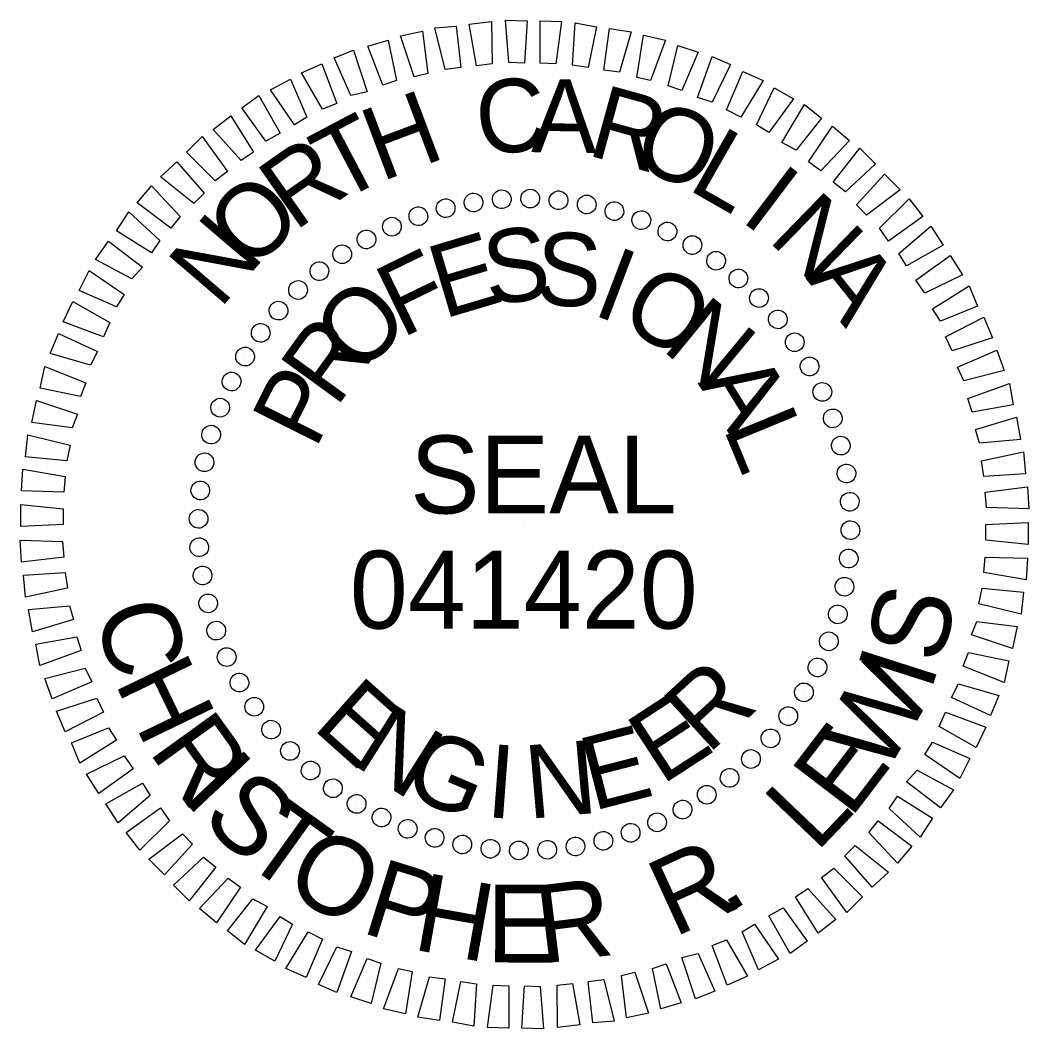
# Model space of a CAD drawing. Extents: x 573468 to 580768, y -57414 to -51768.
# Drawn here: x 580690.5 to 580768.1, y -56457.1 to -56379.5 of the extents above; entities that cross this region are included whole.
import ezdxf

# ---------------------------------------------------------------- set-up
doc = ezdxf.new("R2010")
doc.units = 0
doc.layers.add('Sheet PE Seal Cell', color=7, linetype='Continuous')

msp = doc.modelspace()

# ---------------------------------------------------------------- linework, layer by layer
at = {"layer": 'Sheet PE Seal Cell'}
for p, q in [((580727.529, -56393.239), (580727.529, -56393.239)), ((580729.729, -56393.189), (580729.729, -56393.189)), ((580731.929, -56393.339), (580731.929, -56393.339)), ((580723.179, -56393.939), (580723.179, -56393.939)), ((580725.379, -56393.539), (580725.379, -56393.539)), ((580734.079, -56393.689), (580734.079, -56393.689)), ((580736.179, -56394.139), (580736.179, -56394.139)), ((580721.079, -56394.539), (580721.079, -56394.539)), ((580738.279, -56394.839), (580738.279, -56394.839)), ((580719.079, -56395.339), (580719.079, -56395.339)), ((580740.279, -56395.739), (580740.279, -56395.739)), ((580717.129, -56396.339), (580717.129, -56396.339)), ((580742.229, -56396.739), (580742.229, -56396.739)), ((580715.229, -56397.489), (580715.229, -56397.489)), ((580744.029, -56397.989), (580744.029, -56397.989)), ((580713.479, -56398.739), (580713.479, -56398.739)), ((580745.779, -56399.339), (580745.779, -56399.339)), ((580711.829, -56400.239), (580711.829, -56400.239)), ((580747.329, -56400.839), (580747.329, -56400.839)), ((580710.329, -56401.789), (580710.329, -56401.789)), ((580748.829, -56402.489), (580748.829, -56402.489)), ((580708.979, -56403.539), (580708.979, -56403.539)), ((580750.079, -56404.239), (580750.079, -56404.239)), ((580707.729, -56405.339), (580707.729, -56405.339)), ((580751.229, -56406.139), (580751.229, -56406.139)), ((580706.729, -56407.289), (580706.729, -56407.289)), ((580752.229, -56408.089), (580752.229, -56408.089)), ((580705.829, -56409.289), (580705.829, -56409.289)), ((580753.029, -56410.089), (580753.029, -56410.089)), ((580705.129, -56411.389), (580705.129, -56411.389)), ((580753.629, -56412.189), (580753.629, -56412.189)), ((580704.679, -56413.489), (580704.679, -56413.489)), ((580754.029, -56414.389), (580754.029, -56414.389)), ((580704.329, -56415.639), (580704.329, -56415.639)), ((580754.329, -56416.539), (580754.329, -56416.539)), ((580704.179, -56417.839), (580704.179, -56417.839)), ((580729.279, -56418.289), (580729.279, -56418.289)), ((580754.379, -56418.739), (580754.379, -56418.739)), ((580704.229, -56420.039), (580704.229, -56420.039)), ((580754.229, -56420.939), (580754.229, -56420.939)), ((580704.529, -56422.189), (580704.529, -56422.189)), ((580753.879, -56423.089), (580753.879, -56423.089)), ((580704.929, -56424.389), (580704.929, -56424.389)), ((580753.429, -56425.189), (580753.429, -56425.189)), ((580705.529, -56426.489), (580705.529, -56426.489)), ((580752.729, -56427.289), (580752.729, -56427.289)), ((580706.329, -56428.489), (580706.329, -56428.489)), ((580751.829, -56429.289), (580751.829, -56429.289)), ((580707.329, -56430.439), (580707.329, -56430.439)), ((580750.829, -56431.239), (580750.829, -56431.239)), ((580708.479, -56432.339), (580708.479, -56432.339)), ((580749.579, -56433.039), (580749.579, -56433.039)), ((580709.729, -56434.089), (580709.729, -56434.089)), ((580748.229, -56434.789), (580748.229, -56434.789)), ((580711.229, -56435.739), (580711.229, -56435.739)), ((580746.729, -56436.339), (580746.729, -56436.339)), ((580712.779, -56437.239), (580712.779, -56437.239)), ((580745.079, -56437.839), (580745.079, -56437.839)), ((580714.529, -56438.589), (580714.529, -56438.589)), ((580743.329, -56439.089), (580743.329, -56439.089)), ((580716.329, -56439.839), (580716.329, -56439.839)), ((580741.429, -56440.239), (580741.429, -56440.239)), ((580718.279, -56440.839), (580718.279, -56440.839)), ((580739.479, -56441.239), (580739.479, -56441.239)), ((580720.279, -56441.739), (580720.279, -56441.739)), ((580737.479, -56442.039), (580737.479, -56442.039)), ((580722.379, -56442.439), (580722.379, -56442.439)), ((580724.479, -56442.889), (580724.479, -56442.889)), ((580733.179, -56443.039), (580733.179, -56443.039)), ((580735.379, -56442.639), (580735.379, -56442.639)), ((580726.629, -56443.239), (580726.629, -56443.239)), ((580728.829, -56443.389), (580728.829, -56443.389)), ((580731.029, -56443.339), (580731.029, -56443.339))]:
    msp.add_line(p, q, dxfattribs=at)
for points in [[(580728.079, -56382.739), (580727.829, -56379.489), (580729.479, -56379.539), (580729.279, -56382.789)], [(580723.179, -56383.289), (580722.379, -56380.089), (580724.029, -56379.939), (580724.379, -56383.139)], [(580725.579, -56382.989), (580725.029, -56379.789), (580726.729, -56379.589), (580726.779, -56382.839)], [(580730.479, -56382.789), (580730.479, -56379.539), (580732.129, -56379.589), (580731.679, -56382.839)], [(580732.979, -56382.939), (580733.179, -56379.689), (580734.829, -56379.989), (580734.179, -56383.139)], [(580735.379, -56383.339), (580735.829, -56380.139), (580737.479, -56380.389), (580736.579, -56383.489)], [(580718.379, -56384.489), (580717.229, -56381.489), (580718.779, -56381.039), (580719.429, -56384.139)], [(580720.779, -56383.839), (580719.729, -56380.689), (580721.429, -56380.339), (580721.829, -56383.589)], [(580737.929, -56383.889), (580738.429, -56380.639), (580740.129, -56381.039), (580738.979, -56384.139)], [(580715.929, -56385.289), (580714.629, -56382.389), (580716.129, -56381.789), (580717.179, -56384.989)], [(580740.329, -56384.539), (580741.079, -56381.439), (580742.629, -56381.939), (580741.379, -56384.889)], [(580742.579, -56385.439), (580743.729, -56382.289), (580745.129, -56382.889), (580743.729, -56385.789)], [(580713.729, -56386.339), (580712.129, -56383.539), (580713.679, -56382.839), (580714.829, -56385.889)], [(580711.579, -56387.539), (580709.729, -56384.839), (580711.279, -56384.039), (580712.529, -56386.939)], [(580744.829, -56386.389), (580746.079, -56383.439), (580747.629, -56384.139), (580745.929, -56386.939)], [(580747.129, -56387.539), (580748.479, -56384.689), (580749.979, -56385.539), (580748.079, -56388.139)], [(580709.379, -56388.789), (580707.529, -56386.239), (580708.829, -56385.289), (580710.479, -56388.189)], [(580749.079, -56388.889), (580750.829, -56385.989), (580752.129, -56387.039), (580750.179, -56389.489)], [(580707.479, -56390.289), (580705.329, -56387.889), (580706.679, -56386.839), (580708.429, -56389.639)], [(580751.129, -56390.389), (580752.979, -56387.639), (580754.279, -56388.739), (580752.079, -56391.089)], [(580705.479, -56391.839), (580703.279, -56389.639), (580704.479, -56388.439), (580706.429, -56391.139)], [(580753.029, -56391.939), (580755.079, -56389.339), (580756.279, -56390.539), (580753.979, -56392.689)], [(580703.829, -56393.589), (580701.279, -56391.539), (580702.529, -56390.389), (580704.629, -56392.789)], [(580754.829, -56393.689), (580756.979, -56391.339), (580758.179, -56392.539), (580755.579, -56394.489)], [(580702.079, -56395.489), (580699.479, -56393.539), (580700.579, -56392.239), (580702.779, -56394.589)], [(580756.579, -56395.489), (580758.879, -56393.239), (580759.929, -56394.589), (580757.279, -56396.489)], [(580700.579, -56397.389), (580697.879, -56395.689), (580698.829, -56394.239), (580701.229, -56396.439)], [(580758.079, -56397.439), (580760.529, -56395.339), (580761.479, -56396.789), (580758.679, -56398.389)], [(580699.079, -56399.389), (580696.279, -56397.889), (580697.279, -56396.489), (580699.879, -56398.489)], [(580759.379, -56399.489), (580762.029, -56397.589), (580762.979, -56399.089), (580760.079, -56400.489)], [(580697.879, -56401.539), (580695.029, -56400.289), (580695.779, -56398.739), (580698.479, -56400.589)], [(580760.679, -56401.689), (580763.479, -56399.939), (580764.129, -56401.489), (580761.279, -56402.639)], [(580696.879, -56403.839), (580693.779, -56402.689), (580694.529, -56401.139), (580697.379, -56402.739)], [(580761.679, -56403.839), (580764.629, -56402.339), (580765.279, -56403.939), (580762.179, -56404.939)], [(580695.879, -56406.039), (580692.779, -56405.139), (580693.429, -56403.589), (580696.429, -56404.989)], [(580762.579, -56406.189), (580765.629, -56404.889), (580766.179, -56406.439), (580763.079, -56407.239)], [(580695.129, -56408.439), (580692.029, -56407.789), (580692.379, -56406.139), (580695.529, -56407.389)], [(580763.379, -56408.589), (580766.579, -56407.439), (580766.879, -56409.089), (580763.729, -56409.639)], [(580694.479, -56410.839), (580691.379, -56410.439), (580691.729, -56408.739), (580694.879, -56409.789)], [(580763.979, -56410.989), (580767.129, -56410.039), (580767.429, -56411.739), (580764.279, -56412.039)], [(580694.079, -56413.389), (580690.879, -56413.089), (580691.079, -56411.389), (580694.329, -56412.189)], [(580764.429, -56413.389), (580767.679, -56412.689), (580767.829, -56414.389), (580764.629, -56414.589)], [(580693.829, -56415.789), (580690.579, -56415.689), (580690.679, -56414.039), (580693.929, -56414.589)], [(580764.729, -56415.789), (580767.979, -56415.389), (580768.079, -56417.089), (580764.829, -56416.989)], [(580693.779, -56418.289), (580690.529, -56418.439), (580690.529, -56416.739), (580693.779, -56417.089)], [(580764.779, -56418.289), (580768.029, -56418.139), (580768.029, -56419.839), (580764.779, -56419.489)], [(580693.829, -56420.789), (580690.579, -56421.189), (580690.479, -56419.489), (580693.729, -56419.589)], [(580764.729, -56420.789), (580767.979, -56420.889), (580767.879, -56422.539), (580764.629, -56421.989)], [(580694.129, -56423.189), (580690.879, -56423.889), (580690.729, -56422.189), (580693.929, -56421.989)], [(580764.479, -56423.189), (580767.679, -56423.489), (580767.479, -56425.189), (580764.229, -56424.389)], [(580694.579, -56425.589), (580691.429, -56426.539), (580691.129, -56424.839), (580694.279, -56424.539)], [(580764.079, -56425.739), (580767.179, -56426.139), (580766.829, -56427.839), (580763.679, -56426.789)], [(580695.179, -56427.989), (580691.979, -56429.139), (580691.679, -56427.489), (580694.829, -56426.939)], [(580763.429, -56428.139), (580766.529, -56428.789), (580766.179, -56430.439), (580763.029, -56429.189)], [(580695.979, -56430.389), (580692.929, -56431.689), (580692.379, -56430.139), (580695.479, -56429.339)], [(580762.679, -56430.539), (580765.779, -56431.439), (580765.129, -56432.989), (580762.129, -56431.589)], [(580696.879, -56432.739), (580693.929, -56434.239), (580693.279, -56432.639), (580696.379, -56431.639)], [(580761.679, -56432.739), (580764.779, -56433.889), (580764.029, -56435.439), (580761.179, -56433.839)], [(580697.879, -56434.889), (580695.079, -56436.639), (580694.429, -56435.089), (580697.279, -56433.939)], [(580760.679, -56435.039), (580763.529, -56436.289), (580762.779, -56437.839), (580760.079, -56435.989)], [(580699.179, -56437.089), (580696.529, -56438.989), (580695.579, -56437.489), (580698.479, -56436.089)], [(580759.479, -56437.189), (580762.279, -56438.689), (580761.279, -56440.089), (580758.679, -56438.089)], [(580700.479, -56439.139), (580698.029, -56441.239), (580697.079, -56439.789), (580699.879, -56438.189)], [(580757.979, -56439.189), (580760.679, -56440.889), (580759.729, -56442.339), (580757.329, -56440.139)], [(580701.979, -56441.089), (580699.679, -56443.339), (580698.629, -56441.989), (580701.279, -56440.089)], [(580756.479, -56441.089), (580759.079, -56443.039), (580757.979, -56444.339), (580755.779, -56441.989)], [(580703.729, -56442.889), (580701.579, -56445.239), (580700.379, -56444.039), (580702.979, -56442.089)], [(580754.729, -56442.989), (580757.279, -56445.039), (580756.029, -56446.189), (580753.929, -56443.789)], [(580705.529, -56444.639), (580703.479, -56447.239), (580702.279, -56446.039), (580704.579, -56443.889)], [(580753.079, -56444.739), (580755.279, -56446.939), (580754.079, -56448.139), (580752.129, -56445.439)], [(580707.429, -56446.189), (580705.579, -56448.939), (580704.279, -56447.839), (580706.479, -56445.489)], [(580751.079, -56446.289), (580753.229, -56448.689), (580751.879, -56449.739), (580750.129, -56446.939)], [(580709.479, -56447.689), (580707.729, -56450.589), (580706.429, -56449.539), (580708.379, -56447.089)], [(580749.179, -56447.789), (580751.029, -56450.339), (580749.729, -56451.289), (580748.079, -56448.389)], [(580711.429, -56449.039), (580710.079, -56451.889), (580708.579, -56451.039), (580710.479, -56448.439)], [(580746.979, -56449.039), (580748.829, -56451.739), (580747.279, -56452.539), (580746.029, -56449.639)], [(580713.729, -56450.189), (580712.479, -56453.139), (580710.929, -56452.439), (580712.629, -56449.639)], [(580715.979, -56451.139), (580714.829, -56454.289), (580713.429, -56453.689), (580714.829, -56450.789)], [(580744.829, -56450.239), (580746.429, -56453.039), (580744.879, -56453.739), (580743.729, -56450.689)], [(580742.629, -56451.289), (580743.929, -56454.189), (580742.429, -56454.789), (580741.379, -56451.589)], [(580718.229, -56452.039), (580717.479, -56455.139), (580715.929, -56454.639), (580717.179, -56451.689)], [(580720.629, -56452.689), (580720.129, -56455.939), (580718.429, -56455.539), (580719.579, -56452.439)], [(580740.179, -56452.089), (580741.329, -56455.089), (580739.779, -56455.539), (580739.129, -56452.439)], [(580723.179, -56453.239), (580722.729, -56456.439), (580721.079, -56456.189), (580721.979, -56453.089)], [(580737.779, -56452.739), (580738.829, -56455.889), (580737.129, -56456.239), (580736.729, -56452.989)], [(580725.579, -56453.639), (580725.379, -56456.889), (580723.729, -56456.589), (580724.379, -56453.439)], [(580728.079, -56453.789), (580728.079, -56457.039), (580726.429, -56456.989), (580726.879, -56453.739)], [(580730.479, -56453.839), (580730.729, -56457.089), (580729.079, -56457.039), (580729.279, -56453.789)], [(580732.979, -56453.589), (580733.529, -56456.789), (580731.829, -56456.989), (580731.779, -56453.739)], [(580735.379, -56453.289), (580736.179, -56456.489), (580734.529, -56456.639), (580734.179, -56453.439)]]:
    msp.add_lwpolyline(points, close=True, dxfattribs=at)
for centre, major_axis in [((580727.529, -56393.27), (-0.05, 0.718)), ((580729.716, -56393.212), (0.013, 0.72)), ((580731.9, -56393.346), (0.075, 0.716)), ((580723.211, -56393.954), (-0.174, 0.699)), ((580725.355, -56393.517), (-0.113, 0.711)), ((580734.064, -56393.669), (0.137, 0.707)), ((580736.192, -56394.18), (0.198, 0.692)), ((580721.113, -56394.575), (-0.234, 0.681)), ((580738.266, -56394.874), (0.258, 0.672)), ((580719.078, -56395.377), (-0.293, 0.658)), ((580740.273, -56395.747), (0.316, 0.647)), ((580717.12, -56396.353), (-0.349, 0.63)), ((580742.196, -56396.791), (0.371, 0.617)), ((580715.254, -56397.496), (-0.403, 0.597)), ((580744.02, -56397.998), (0.423, 0.582)), ((580713.495, -56398.798), (-0.453, 0.56)), ((580745.733, -56399.36), (0.472, 0.543)), ((580711.857, -56400.248), (-0.5, 0.518)), ((580747.32, -56400.867), (0.518, 0.5)), ((580710.35, -56401.835), (-0.543, 0.472)), ((580748.769, -56402.505), (0.56, 0.453)), ((580708.988, -56403.547), (-0.582, 0.423)), ((580750.071, -56404.264), (0.597, 0.403)), ((580707.781, -56405.371), (-0.617, 0.371)), ((580751.214, -56406.13), (0.63, 0.349)), ((580706.737, -56407.294), (-0.647, 0.316)), ((580752.19, -56408.088), (0.658, 0.293)), ((580705.864, -56409.301), (-0.672, 0.258)), ((580752.992, -56410.123), (0.681, 0.234)), ((580705.17, -56411.376), (-0.692, 0.198)), ((580753.614, -56412.221), (0.699, 0.174)), ((580704.659, -56413.503), (-0.707, 0.137)), ((580754.05, -56414.365), (0.711, 0.113)), ((580704.336, -56415.667), (-0.716, 0.075)), ((580754.297, -56416.539), (0.718, 0.05)), ((580704.202, -56417.851), (-0.72, 0.013)), ((580754.355, -56418.726), (0.72, -0.013)), ((580704.26, -56420.038), (-0.718, -0.05)), ((580754.221, -56420.91), (0.716, -0.075)), ((580704.507, -56422.212), (-0.711, -0.113)), ((580753.898, -56423.074), (0.707, -0.137)), ((580704.944, -56424.356), (-0.699, -0.174)), ((580753.387, -56425.202), (0.692, -0.198)), ((580705.565, -56426.454), (-0.681, -0.234)), ((580752.693, -56427.276), (0.672, -0.258)), ((580706.367, -56428.49), (-0.658, -0.293)), ((580751.82, -56429.283), (0.647, -0.316)), ((580707.343, -56430.448), (-0.63, -0.349)), ((580750.776, -56431.206), (0.617, -0.371)), ((580708.486, -56432.313), (-0.597, -0.403)), ((580749.569, -56433.03), (0.582, -0.423)), ((580709.788, -56434.072), (-0.56, -0.453)), ((580748.207, -56434.743), (0.543, -0.472)), ((580711.238, -56435.711), (-0.518, -0.5)), ((580746.701, -56436.33), (0.5, -0.518)), ((580712.825, -56437.217), (-0.472, -0.543)), ((580745.062, -56437.779), (0.453, -0.56)), ((580714.537, -56438.579), (-0.423, -0.582)), ((580743.303, -56439.081), (0.403, -0.597)), ((580716.361, -56439.786), (-0.371, -0.617)), ((580718.284, -56440.83), (-0.316, -0.647)), ((580741.438, -56440.224), (0.349, -0.63)), ((580739.48, -56441.2), (0.293, -0.658)), ((580720.291, -56441.703), (-0.258, -0.672)), ((580737.444, -56442.002), (0.234, -0.681)), ((580722.366, -56442.397), (-0.198, -0.692)), ((580724.493, -56442.908), (-0.137, -0.707)), ((580733.202, -56443.06), (0.113, -0.711)), ((580735.346, -56442.624), (0.174, -0.699)), ((580726.657, -56443.231), (-0.075, -0.716)), ((580728.841, -56443.365), (-0.013, -0.72)), ((580731.028, -56443.307), (0.05, -0.718))]:
    msp.add_ellipse(centre, major_axis=major_axis, ratio=0.999708, dxfattribs=at)

# ---------------------------------------------------------------- texts
for s, height, rotation, p in [('C', 5.638, 6.21987, (580725.829, -56389.939)), ('A', 5.638, 359.02032, (580729.779, -56389.639)), ('R', 5.638, 344.6211, (580733.979, -56389.839)), ('H', 5.638, 20.61948, (580718.229, -56391.939)), ('O', 5.638, 337.42116, (580737.329, -56390.589)), ('T', 5.638, 27.81977, (580714.979, -56393.589)), ('L', 5.638, 330.22088, (580741.729, -56392.439)), ('R', 5.639, 35.02051, (580711.579, -56395.789)), ('I', 5.638, 323.02014, (580745.779, -56394.839)), ('O', 5.639, 42.22174, (580708.129, -56398.889)), ('N', 5.639, 315.81891, (580747.929, -56396.389)), ('N', 5.639, 49.4235, (580705.829, -56401.789)), ('E', 5.638, 16.61107, (580723.029, -56402.489)), ('S', 5.638, 7.25561, (580726.479, -56401.439)), ('S', 5.638, 357.9004, (580730.079, -56401.389)), ('F', 5.638, 25.96703, (580719.829, -56403.989)), ('I', 5.638, 339.1896, (580734.379, -56402.089)), ('A', 5.639, 308.61715, (580750.879, -56399.339)), ('O', 5.638, 329.83348, (580736.379, -56402.789)), ('O', 5.639, 44.68124, (580716.529, -56406.939)), ('N', 5.639, 320.47661, (580739.729, -56404.789)), ('R', 5.639, 54.03965, (580714.779, -56409.389)), ('P', 5.639, 63.39889, (580713.179, -56412.589)), ('A', 5.639, 301.76027, (580742.579, -56407.389)), ('L', 5.639, 292.40085, (580744.529, -56410.839)), ('SEAL', 5.9982, 360, (580720.48, -56417.44)), ('S', 5.998, 76.05447, (580761.307, -56429.145)), ('C', 5.998, 286.20197, (580696.13, -56424.986)), ('W', 5.998, 59.71844, (580756.96, -56437.716)), ('I', 5.998, 72.25252, (580760.516, -56431.245)), ('H', 5.998, 295.78413, (580697.707, -56430.41)), ('R', 5.639, 42.48141, (580743.379, -56436.039)), ('E', 5.638, 318.27689, (580712.879, -56433.939)), ('E', 5.638, 33.12409, (580739.829, -56438.389)), ('N', 5.639, 327.63396, (580715.879, -56436.639)), ('R', 5.998, 305.76811, (580700.287, -56435.7)), ('E', 5.638, 14.41176, (580734.529, -56440.339)), ('E', 5.998, 52.60911, (580754.343, -56440.992)), ('G', 5.638, 336.99024, (580719.679, -56438.889)), ('I', 5.638, 355.7012, (580726.229, -56440.789)), ('N', 5.638, 5.05639, (580729.579, -56440.939)), ('I', 5.998, 313.24837, (580702.801, -56439.326)), ('S', 5.998, 317.05032, (580704.254, -56441.036)), ('L', 5.998, 46.33434, (580751.711, -56443.596)), ('T', 5.998, 324.37603, (580707.359, -56444.041)), ('O', 5.998, 331.17627, (580710.562, -56446.455)), ('R', 5.998, 24.61995, (580740.756, -56450.099)), ('P', 5.998, 342.73667, (580716.586, -56449.635)), ('H', 5.998, 349.84601, (580720.563, -56450.964)), ('E', 5.998, 359.82999, (580726.361, -56451.981)), ('R', 5.998, 6.93933, (580730.553, -56452.083)), ('.', 5.998, 32.10021, (580744.8, -56448.335))]:
    msp.add_text(s, height=height, rotation=rotation, dxfattribs=at).set_placement(p)
msp.add_text('041420', height=5.9982, dxfattribs=at).set_placement((580715.839, -56426.297))

doc.saveas('drawing.dxf')
